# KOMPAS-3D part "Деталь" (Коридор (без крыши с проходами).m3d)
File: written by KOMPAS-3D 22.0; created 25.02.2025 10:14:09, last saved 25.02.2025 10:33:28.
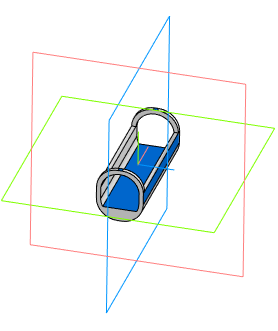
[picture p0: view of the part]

Document properties: Автор: Пользователь Windows; Полное имя файла: C:\Users\Student\Documents\Картошечка\База Сабнатика\Коридор\Коридор (без крфши с проходами).m3d

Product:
- Part/product: Деталь
    Масса: 0.008372

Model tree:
1. Эскиз:1
2. Элемент выдавливания:1
     Расстояние 1 = 30
3. Эскиз:2  (with: Элемент выдавливания:1)
4. Элемент выдавливания:2
     Расстояние 2 = 5
5. Оболочка:1  (with: Элемент выдавливания:2)
     Толщина стенки 2 = 1
6. Эскиз:3  (with: Оболочка:1)
7. Элемент выдавливания:3
     Расстояние 1 = 28
8. Эскиз:4  (with: Оболочка:1)
9. Элемент выдавливания:4
     Расстояние 1 = 32; Расстояние 2 = 1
